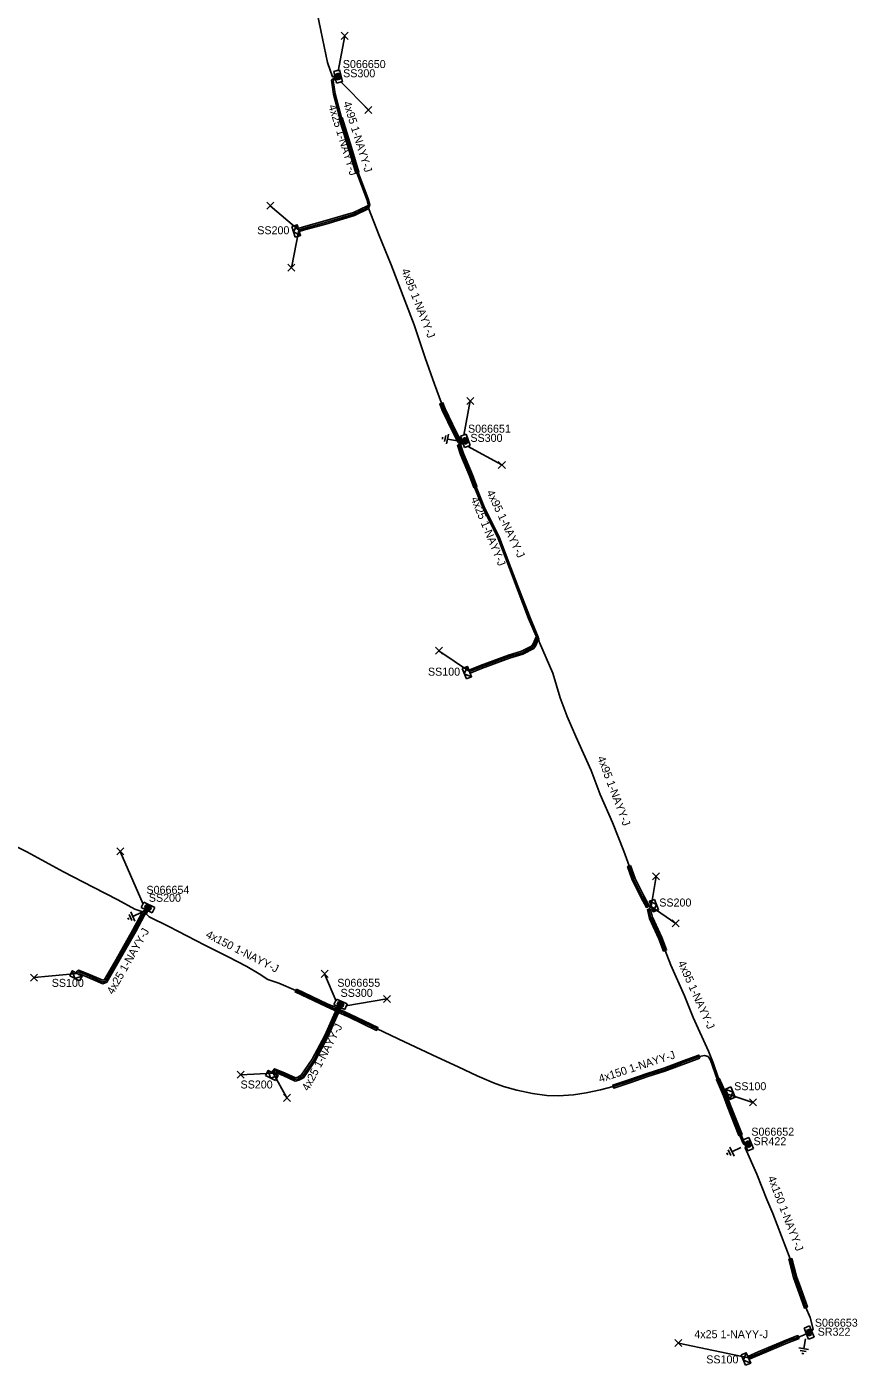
# Model space of a CAD drawing. Extents: x -748492 to -735633, y -1146251 to -1139940.
# Drawn here: x -736915.6 to -736811.8, y -1145364.4 to -1145197.1 of the extents above; entities that cross this region are included whole.
import ezdxf

# ---------------------------------------------------------------- set-up
doc = ezdxf.new("R2010")
doc.units = 0
for name, color, linetype in [('Vrstva 1', 7, 'Continuous'), ('Vrstva 14', 7, 'Continuous'), ('Vrstva 15', 7, 'Continuous'), ('Vrstva 20', 7, 'Continuous'), ('Vrstva 28', 7, 'Continuous'), ('Vrstva 29', 7, 'Continuous'), ('Vrstva 30', 7, 'Continuous'), ('Vrstva 31', 7, 'Continuous'), ('Vrstva 33', 7, 'Continuous'), ('Vrstva 34', 7, 'Continuous'), ('Vrstva 5', 7, 'Continuous'), ('Vrstva 59', 7, 'Continuous'), ('Vrstva 6', 7, 'Continuous'), ('Vrstva 8', 7, 'Continuous'), ('Vrstva 9', 7, 'Continuous')]:
    doc.layers.add(name, color=color, linetype=linetype)

# ---------------------------------------------------------------- blocks, each defined once
blk = doc.blocks.new('NN800')
at = {"layer": 'Vrstva 1'}
for points in [[(-0.44, 0.44), (0.44, -0.44)], [(-0.44, -0.44), (0.44, 0.44)]]:
    blk.add_lwpolyline(points, dxfattribs=at)
blk = doc.blocks.new('NN620')
at = {"layer": 'Vrstva 8'}
for points in [[(0.75, 0), (-0.75, 0)], [(-0.75, 0), (-0.75, -0.75)], [(0.75, -0.75), (0.75, 0)], [(-0.75, -0.75), (0.75, -0.75)], [(0.37, -0.18), (-0.38, -0.18)], [(-0.38, -0.18), (-0.38, -0.56)], [(-0.38, -0.56), (0.37, -0.56)], [(0.32, -0.23), (-0.33, -0.23)], [(-0.33, -0.23), (-0.33, -0.51)], [(-0.33, -0.51), (0.32, -0.51)], [(0.27, -0.27), (-0.28, -0.27)], [(-0.28, -0.27), (-0.28, -0.46)], [(-0.28, -0.46), (0.27, -0.46)], [(0.23, -0.32), (-0.23, -0.32)], [(-0.23, -0.32), (-0.23, -0.42)], [(-0.23, -0.42), (0.23, -0.42)], [(-0.19, -0.37), (0.19, -0.37)], [(0.23, -0.42), (0.23, -0.32)], [(0.27, -0.46), (0.27, -0.27)], [(0.32, -0.51), (0.32, -0.23)], [(0.37, -0.56), (0.37, -0.18)]]:
    blk.add_lwpolyline(points, dxfattribs=at)
blk = doc.blocks.new('NN630')
at = {"layer": 'Vrstva 9'}
for points in [[(0, -0.7), (-0.7, 0)], [(-0.7, -0.7), (-0.7, 0), (0.7, 0), (0.7, -0.7)], [(-0.7, -0.7), (0.7, -0.7)], [(0, -0.7), (0.7, 0)]]:
    blk.add_lwpolyline(points, dxfattribs=at)
blk = doc.blocks.new('NN810')
at = {"layer": 'Vrstva 14'}
for points in [[(0, -0.64), (0, -1.89)], [(0.63, -1.89), (-0.62, -1.89)], [(0.39, -2.2), (-0.4, -2.2)], [(0, -2.52), (-0.12, -2.52)], [(0.14, -2.52), (0, -2.52)]]:
    blk.add_lwpolyline(points, dxfattribs=at)

msp = doc.modelspace()

# ---------------------------------------------------------------- linework, layer by layer
at = {"layer": 'Vrstva 20'}
for points in [[(-736876.18, -1145208.48), (-736875.02, -1145212.23), (-736874.07, -1145215.31), (-736874.45, -1145215.43), (-736875.4, -1145212.35), (-736876.56, -1145208.6)], [(-736872.83, -1145219.87), (-736874.63, -1145220.74), (-736878.22, -1145221.79), (-736880.89, -1145222.53), (-736881.53, -1145222.74), (-736881.65, -1145222.36), (-736881.01, -1145222.15), (-736878.32, -1145221.41), (-736874.77, -1145220.36), (-736873.01, -1145219.51)], [(-736861.67, -1145249.1), (-736862.28, -1145247.96), (-736863.66, -1145245.05), (-736863.96, -1145244.26), (-736863.58, -1145244.12), (-736863.3, -1145244.89), (-736861.92, -1145247.78), (-736861.31, -1145248.92)], [(-736861.38, -1145249.33), (-736861.02, -1145250.47), (-736859.9, -1145253.14), (-736859.34, -1145254.59), (-736859.72, -1145254.73), (-736860.28, -1145253.28), (-736861.4, -1145250.61), (-736861.76, -1145249.45)], [(-736851.59, -1145273.56), (-736851.96, -1145274.46), (-736852.22, -1145274.83), (-736853.59, -1145275.57), (-736855.25, -1145276.05), (-736858.75, -1145277.34), (-736860.19, -1145277.92), (-736860.33, -1145277.54), (-736858.89, -1145276.96), (-736855.37, -1145275.67), (-736853.75, -1145275.19), (-736852.5, -1145274.53), (-736852.32, -1145274.26), (-736851.95, -1145273.4)], [(-736840.14, -1145301.95), (-736839.57, -1145303.58), (-736838.49, -1145305.75), (-736837.8, -1145307.01), (-736838.16, -1145307.21), (-736838.85, -1145305.93), (-736839.93, -1145303.74), (-736840.52, -1145302.09)], [(-736900.45, -1145307.68), (-736900.86, -1145308.16), (-736901.96, -1145310.22), (-736904.07, -1145313.91), (-736905.57, -1145316.55), (-736906.06, -1145316.75), (-736908.29, -1145315.78), (-736909.03, -1145315.5), (-736909.13, -1145315.6), (-736909.41, -1145315.3), (-736909.13, -1145315.04), (-736908.15, -1145315.4), (-736906.06, -1145316.31), (-736905.85, -1145316.23), (-736904.41, -1145313.71), (-736902.32, -1145310.02), (-736901.2, -1145307.94), (-736900.75, -1145307.42)], [(-736837.64, -1145307.4), (-736837.41, -1145308.44), (-736836.23, -1145310.96), (-736835.63, -1145312.51), (-736836.01, -1145312.65), (-736836.59, -1145311.12), (-736837.79, -1145308.58), (-736838.04, -1145307.48)], [(-736881.87, -1145317.4), (-736878.03, -1145319.24), (-736876.92, -1145319.73), (-736877.08, -1145320.09), (-736878.19, -1145319.6), (-736882.05, -1145317.76)], [(-736876.34, -1145319.72), (-736877.98, -1145323.39), (-736879.56, -1145326.38), (-736881, -1145328.48), (-736881.58, -1145328.8), (-736882.05, -1145328.91), (-736883.46, -1145328.27), (-736884.5, -1145327.84), (-736884.63, -1145328.02), (-736884.95, -1145327.78), (-736884.64, -1145327.36), (-736883.3, -1145327.91), (-736882.01, -1145328.49), (-736881.72, -1145328.42), (-736881.28, -1145328.18), (-736879.9, -1145326.18), (-736878.34, -1145323.21), (-736876.7, -1145319.56)], [(-736876.37, -1145320), (-736875.12, -1145320.57), (-736871.7, -1145322.21), (-736871.88, -1145322.57), (-736875.28, -1145320.93), (-736876.53, -1145320.36)], [(-736831.47, -1145326.03), (-736832.96, -1145326.57), (-736835.85, -1145327.68), (-736837.96, -1145328.32), (-736840.09, -1145329.08), (-736842.24, -1145329.78), (-736842.36, -1145329.4), (-736840.21, -1145328.7), (-736838.08, -1145327.94), (-736835.99, -1145327.3), (-736833.1, -1145326.19), (-736831.61, -1145325.65)], [(-736829.06, -1145328.53), (-736828.17, -1145330.58), (-736828.53, -1145330.74), (-736829.42, -1145328.69)], [(-736828.16, -1145330.59), (-736827.68, -1145331.85), (-736826.21, -1145335.58), (-736826.59, -1145335.72), (-736828.06, -1145331.99), (-736828.54, -1145330.73)], [(-736819.99, -1145351.07), (-736819.4, -1145353.32), (-736818.87, -1145354.8), (-736818.04, -1145357.13), (-736818.42, -1145357.27), (-736819.25, -1145354.94), (-736819.78, -1145353.44), (-736820.37, -1145351.17)], [(-736819.09, -1145361.09), (-736820.49, -1145361.62), (-736824.03, -1145363.12), (-736825.32, -1145363.68), (-736825.48, -1145363.32), (-736824.19, -1145362.76), (-736820.63, -1145361.24), (-736819.23, -1145360.71)]]:
    msp.add_lwpolyline(points, close=True, dxfattribs=at)
at = {"layer": 'Vrstva 5'}
for points in [[(-736877.09, -1145203.28), (-736877.4, -1145203.4), (-736878.02, -1145201.61), (-736878.83, -1145197.62), (-736879.78, -1145192.92), (-736880.39, -1145189.56), (-736881.07, -1145186.2), (-736881.6, -1145182.62), (-736882.03, -1145178.49), (-736882.39, -1145174.96), (-736882.86, -1145171.15), (-736882.89, -1145167.13), (-736883.18, -1145163.33), (-736883.14, -1145161.12), (-736882.8, -1145160.88), (-736883.19, -1145160.78), (-736883.42, -1145159.58), (-736883.89, -1145156.58), (-736883.95, -1145154.31), (-736883.62, -1145154.26)], [(-736877.05, -1145203.45), (-736877.49, -1145203.8), (-736877.26, -1145205.55), (-736876.47, -1145208.57), (-736875.31, -1145212.32), (-736874.35, -1145215.4), (-736873.1, -1145218.72), (-736872.92, -1145219.4), (-736873.05, -1145219.75), (-736874.7, -1145220.55), (-736878.27, -1145221.6), (-736880.95, -1145222.34), (-736881.59, -1145222.55)], [(-736861.21, -1145248.88), (-736861.49, -1145249.01), (-736862.1, -1145247.87), (-736863.48, -1145244.97), (-736863.77, -1145244.19), (-736864.64, -1145241.81), (-736865.81, -1145238.51), (-736867.19, -1145234.37), (-736868.36, -1145231.37), (-736870.04, -1145226.9), (-736871.54, -1145223.22), (-736872.87, -1145219.83), (-736872.7, -1145219.41), (-736872.92, -1145218.66), (-736874.17, -1145215.34), (-736875.11, -1145212.26), (-736876.27, -1145208.51), (-736877.06, -1145205.51), (-736877.29, -1145203.86), (-736877.01, -1145203.64)], [(-736861.15, -1145249.02), (-736861.69, -1145249.36), (-736861.3, -1145250.57), (-736860.18, -1145253.25), (-736859.62, -1145254.7), (-736858.59, -1145257.21), (-736856.68, -1145261.08), (-736855.26, -1145264.8), (-736854.18, -1145267.68), (-736852.87, -1145271.09), (-736851.82, -1145273.61), (-736852.14, -1145274.36), (-736852.36, -1145274.68), (-736853.67, -1145275.38), (-736855.31, -1145275.86), (-736858.82, -1145277.15), (-736860.26, -1145277.73)], [(-736825.83, -1145336.77), (-736825.95, -1145336.52), (-736826.31, -1145335.61), (-736827.78, -1145331.88), (-736828.22, -1145330.73), (-736827.99, -1145330.56), (-736828.29, -1145330.54), (-736829.15, -1145328.57), (-736829.83, -1145326.61), (-736830.42, -1145325.18), (-736832.3, -1145320.98), (-736833.38, -1145318.25), (-736835.1, -1145314.43), (-736835.82, -1145312.58), (-736836.41, -1145311.04), (-736837.6, -1145308.51), (-736837.84, -1145307.44), (-736837.55, -1145307.09), (-736837.98, -1145307.11), (-736838.67, -1145305.84), (-736839.75, -1145303.66), (-736840.33, -1145302.02), (-736840.99, -1145300.17), (-736842.38, -1145296.58), (-736843.92, -1145293.09), (-736845.06, -1145290.08), (-736846.97, -1145285.84), (-736848.05, -1145283.35), (-736848.94, -1145280.99), (-736849.83, -1145277.93), (-736851.51, -1145274.1), (-736851.68, -1145273.44), (-736852.69, -1145271.01), (-736854, -1145267.6), (-736855.08, -1145264.74), (-736856.5, -1145261), (-736858.41, -1145257.13), (-736859.44, -1145254.62), (-736860, -1145253.17), (-736861.12, -1145250.51), (-736861.45, -1145249.42), (-736861.09, -1145249.18)], [(-736921.27, -1145297.36), (-736915.56, -1145300.25), (-736910.97, -1145302.76), (-736907.27, -1145304.66), (-736904.21, -1145306.27), (-736902.06, -1145307.43), (-736901.07, -1145307.74), (-736900.75, -1145307.47)], [(-736900.6, -1145307.55), (-736901.03, -1145308.05), (-736902.14, -1145310.12), (-736904.24, -1145313.81), (-736905.71, -1145316.39), (-736906.06, -1145316.53), (-736908.22, -1145315.59), (-736909.08, -1145315.27), (-736909.27, -1145315.45)], [(-736900.45, -1145307.63), (-736900.68, -1145308.02), (-736900.27, -1145308.36), (-736897.83, -1145309.58), (-736893.31, -1145311.92), (-736890.43, -1145313.38), (-736888.1, -1145314.6), (-736886.54, -1145315.52), (-736885.44, -1145316.2), (-736884.07, -1145316.65), (-736881.96, -1145317.58), (-736878.11, -1145319.42), (-736877, -1145319.91), (-736876.66, -1145319.57)], [(-736876.52, -1145319.64), (-736878.16, -1145323.3), (-736879.73, -1145326.28), (-736881.14, -1145328.33), (-736881.65, -1145328.61), (-736882.03, -1145328.7), (-736883.38, -1145328.09), (-736884.57, -1145327.6), (-736884.79, -1145327.9)], [(-736876.37, -1145319.72), (-736876.45, -1145320.18), (-736875.2, -1145320.75), (-736871.79, -1145322.39), (-736868.4, -1145324), (-736864.29, -1145325.92), (-736861.68, -1145327.14), (-736859.29, -1145328.23), (-736857.28, -1145329.12), (-736856.02, -1145329.6), (-736854.34, -1145330.05), (-736852.4, -1145330.45), (-736850.62, -1145330.71), (-736849.14, -1145330.73), (-736847.27, -1145330.63), (-736845.69, -1145330.38), (-736843.9, -1145330), (-736842.3, -1145329.59), (-736840.15, -1145328.89), (-736838.02, -1145328.13), (-736835.92, -1145327.49), (-736833.03, -1145326.38), (-736831.54, -1145325.84), (-736830.91, -1145325.71), (-736830.45, -1145325.83), (-736830.15, -1145326.29), (-736829.33, -1145328.65), (-736828.44, -1145330.71), (-736827.96, -1145331.96), (-736826.49, -1145335.69), (-736826.13, -1145336.62), (-736825.99, -1145336.8), (-736825.77, -1145336.92)], [(-736825.73, -1145337.02), (-736825.8, -1145337.25), (-736824.34, -1145340.54), (-736823.12, -1145343.69), (-736822.36, -1145345.46), (-736820.18, -1145351.12), (-736819.59, -1145353.38), (-736819.06, -1145354.87), (-736818.23, -1145357.2), (-736817.7, -1145358.47), (-736817.33, -1145359.9), (-736817.57, -1145360.25)], [(-736818.18, -1145360.48), (-736818.55, -1145360.66), (-736819.16, -1145360.9), (-736820.56, -1145361.43), (-736824.11, -1145362.94), (-736825.4, -1145363.5)]]:
    msp.add_lwpolyline(points, dxfattribs=at)
at = {"layer": 'Vrstva 59'}
for points in [[(-736876.69, -1145202.69), (-736875.85, -1145198.27)], [(-736876.35, -1145204.01), (-736872.89, -1145207.53)], [(-736881.59, -1145222.55), (-736885.15, -1145219.5)], [(-736881.59, -1145222.55), (-736882.52, -1145227.26)], [(-736860.96, -1145248.17), (-736860.17, -1145243.9)], [(-736860.5, -1145249.54), (-736856.22, -1145251.9)], [(-736860.26, -1145277.73), (-736864.08, -1145275.13)], [(-736901.05, -1145306.78), (-736903.89, -1145300.21)], [(-736837.55, -1145307.09), (-736836.95, -1145303.33)], [(-736837.55, -1145307.09), (-736834.49, -1145309.2)], [(-736909.27, -1145315.45), (-736914.66, -1145315.97)], [(-736876.92, -1145318.92), (-736878.36, -1145315.5)], [(-736875.71, -1145319.5), (-736870.57, -1145318.63)], [(-736884.79, -1145327.9), (-736888.84, -1145328.12)], [(-736884.79, -1145327.9), (-736883.07, -1145331)], [(-736827.99, -1145330.56), (-736824.84, -1145331.57)], [(-736825.4, -1145363.5), (-736834.16, -1145361.64)]]:
    msp.add_lwpolyline(points, dxfattribs=at)

# ---------------------------------------------------------------- block references
at = {"layer": 'Vrstva 15'}
for p, rotation in [((-736861.15, -1145249.02), -100.91601319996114), ((-736900.6, -1145307.55), -65.4978149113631), ((-736825.77, -1145336.92), -64.64016650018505), ((-736818.18, -1145360.48), -10.01012293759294)]:
    msp.add_blockref('NN810', p, dxfattribs=dict(at, rotation=rotation))
at = {"layer": 'Vrstva 28'}
for p, rotation in [((-736877.05, -1145203.45), 103.99419844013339), ((-736861.15, -1145249.02), 109.80143940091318), ((-736900.6, -1145307.55), 153.5437151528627), ((-736876.52, -1145319.64), 155.8634484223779), ((-736825.77, -1145336.92), 112.85677861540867), ((-736818.18, -1145360.48), 112.02850015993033)]:
    msp.add_blockref('NN620', p, dxfattribs=dict(at, rotation=rotation))
at = {"layer": 'Vrstva 31'}
for p, rotation in [((-736881.59, -1145222.55), -71.83404340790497), ((-736860.26, -1145277.73), -68.06151953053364), ((-736837.55, -1145307.09), 110.15535371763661), ((-736909.27, -1145315.45), -27.61024538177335), ((-736884.79, -1145327.9), -26.97961375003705), ((-736827.99, -1145330.56), 113.20668041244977), ((-736825.4, -1145363.5), -66.53392413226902)]:
    msp.add_blockref('NN630', p, dxfattribs=dict(at, rotation=rotation))
at = {"layer": 'Vrstva 34'}
for p in [(-736875.85, -1145198.27), (-736872.89, -1145207.53), (-736885.15, -1145219.5), (-736882.52, -1145227.26), (-736860.17, -1145243.9), (-736856.22, -1145251.9), (-736864.08, -1145275.13), (-736903.89, -1145300.21), (-736836.95, -1145303.33), (-736834.49, -1145309.2), (-736914.66, -1145315.97), (-736878.36, -1145315.5), (-736870.57, -1145318.63), (-736888.84, -1145328.12), (-736883.07, -1145331), (-736824.84, -1145331.57), (-736834.16, -1145361.64)]:
    msp.add_blockref('NN800', p, dxfattribs=at)

# ---------------------------------------------------------------- texts
at = {"layer": 'Vrstva 29'}
for s, p in [('S066650', (-736876.09, -1145202.3)), ('S066651', (-736860.45, -1145247.87)), ('S066654', (-736900.62, -1145305.5)), ('S066655', (-736876.78, -1145317.12)), ('S066652', (-736825.05, -1145335.73)), ('S066653', (-736817.11, -1145359.6))]:
    msp.add_text(s, height=1, dxfattribs=at).set_placement(p)
at = {"layer": 'Vrstva 30'}
for s, p in [('SS300', (-736876.05, -1145203.45)), ('SS300', (-736860.15, -1145249.02)), ('SS200', (-736900.33, -1145306.5)), ('SS300', (-736876.37, -1145318.38)), ('SR422', (-736824.77, -1145336.92)), ('SR322', (-736816.76, -1145360.73))]:
    msp.add_text(s, height=1, dxfattribs=at).set_placement(p)
at = {"layer": 'Vrstva 33'}
for s, p in [('SS200', (-736886.78, -1145223.07)), ('SS100', (-736865.45, -1145278.24)), ('SS200', (-736836.55, -1145307.09)), ('SS100', (-736912.46, -1145317.13)), ('SS200', (-736888.87, -1145329.83)), ('SS100', (-736827.19, -1145330.05)), ('SS100', (-736830.68, -1145364.19))]:
    msp.add_text(s, height=1, dxfattribs=at).set_placement(p)
at = {"layer": 'Vrstva 6'}
for s, rotation, p in [('4x25 1-NAYY-J', 287.176, (-736877.9, -1145207.03)), ('4x95 1-NAYY-J', 287.202, (-736876.06, -1145206.62)), ('4x95 1-NAYY-J', 291.306, (-736868.79, -1145227.57)), ('4x25 1-NAYY-J', 292.318, (-736860.12, -1145256.12)), ('4x95 1-NAYY-J', 295.453, (-736858.16, -1145255.31)), ('4x95 1-NAYY-J', 290.744, (-736844.31, -1145288.5)), ('4x25 1-NAYY-J', 60.356, (-736904.79, -1145318.16)), ('4x150 1-NAYY-J', 333.118, (-736893.3, -1145310.9)), ('4x95 1-NAYY-J', 294.24, (-736834.26, -1145314.12)), ('4x25 1-NAYY-J', 62.218, (-736880.39, -1145330.22)), ('4x150 1-NAYY-J', 18.034, (-736843.94, -1145329.11)), ('4x150 1-NAYY-J', 291.171, (-736823.02, -1145340.97))]:
    msp.add_text(s, height=1, rotation=rotation, dxfattribs=at).set_placement(p)
msp.add_text('4x25 1-NAYY-J', height=1, dxfattribs=at).set_placement((-736832.17, -1145361.04))

doc.saveas('drawing.dxf')
